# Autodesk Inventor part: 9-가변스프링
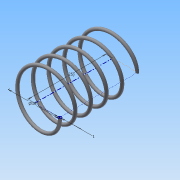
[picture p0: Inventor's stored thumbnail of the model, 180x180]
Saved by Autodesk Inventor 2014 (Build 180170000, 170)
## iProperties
Created: 2015-06
Part Number: 9-가변스프링
Material: 강철, 연강
Document SubType Name: Modeling
Designer: MYHOME
Density: 7.86 g/cm^3
Appearance: 강철
Mass: 1.52988 g
Surface Area: 7.87024 cm^2
Volume: 0.194641 cm^3
Author: MYHOME
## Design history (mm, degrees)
sketch "스케치1"
  geometry: L1 (0, 14.5)-(8, 14.5); L2 (8, 14.5)-(8, 0); L3 (8, 0)-(0, 0); L4 (0, 0)-(0, 14.5); C1 r 0.5 at (8, 0); 1 further point
  constraints: 8 end point, 3 coincident, 2 parallel, 1 centre point, 1 horizontal, 1 perpendicular
  dimensions: "d0" = 1 diameter of C1; "d1" = 16 diameter of L2 L4; "d2" = 14.5 distance of L3.end L1.start (derived)
feature "코일1" sketch "스케치1" pitch "d3" = 10; turns "d5" = 5; dims "d4" = 14.5 (= d2), "d6" = 0, angle "d7" = 90 deg, angle "d8" = 90 deg, "d9" = 0, "d10" = 0
sketch "스케치2"
  geometry: L1 (-8.5, 0)-(-7.5, 0) reference; 1 further point
  constraints: 1 horizontal alignment
extrude "돌출1" cut sketch "스케치2" stored distance "d11" = 10; taper "d12" = 0 deg
node "작업 평면1"
sketch "스케치3"
  geometry: L1 (-7.5, 0)-(-8.5, 0) reference; 1 further point
  constraints: 1 horizontal alignment
extrude "돌출2" cut sketch "스케치3" stored distance "d14" = 10; taper "d15" = 0 deg
node "솔리드1"
node "절단 모서리 투영1"
node "절단 모서리 투영2"
other parameters: "d13" = 14.5 (= d2)
